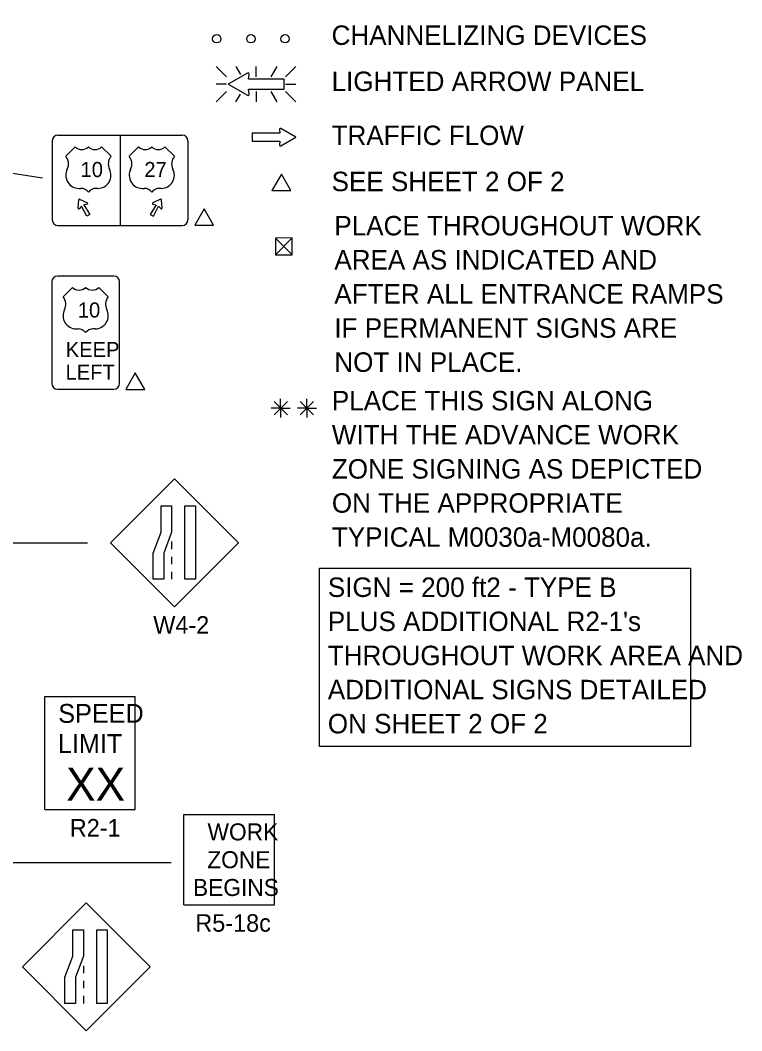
# Model space of a CAD drawing. Extents: x 16731 to 18475, y 7005 to 8303.
# Drawn here: x 17095.5 to 17440.1, y 7483 to 7965.9 of the extents above; entities that cross this region are included whole.
import ezdxf

# ---------------------------------------------------------------- set-up
doc = ezdxf.new("R2010")
doc.units = 0
for name, color, linetype in [('ALI_LEGAL_EX', 7, 'Continuous'), ('MT_SCRATCH_LEVEL_E', 7, 'Continuous'), ('PAVT_EDGE_EX', 7, 'Continuous'), ('TRAFFIC_SIGNS_PR', 7, 'Continuous'), ('TYPICAL_EX', 7, 'Continuous'), ('TYPICAL_TEXT_DIMEN_EX', 7, 'Continuous'), ('TYPICAL_TEXT_DIMEN_PR', 7, 'Continuous')]:
    doc.layers.add(name, color=color, linetype=linetype)

msp = doc.modelspace()

# ---------------------------------------------------------------- linework, layer by layer
at = {"layer": 'ALI_LEGAL_EX'}
msp.add_arc((17317.23, 7890.11), 340, 129.5666, 180, dxfattribs=at)
at = {"layer": 'MT_SCRATCH_LEVEL_E'}
for p, q in [((17219.57, 7911.9), (17206.32, 7911.9)), ((17206.32, 7911.9), (17206.32, 7908.16)), ((17219.57, 7911.9), (17206.32, 7911.9)), ((17206.32, 7911.9), (17206.32, 7908.16)), ((17219.26, 7913.68), (17219.57, 7911.9)), ((17219.26, 7913.68), (17219.57, 7911.9)), ((17227.18, 7910.05), (17219.94, 7914.16)), ((17227.18, 7910.05), (17219.94, 7914.16)), ((17219.94, 7905.9), (17227.18, 7910.05)), ((17219.94, 7905.9), (17227.18, 7910.05)), ((17206.32, 7908.16), (17219.57, 7908.16)), ((17206.32, 7908.16), (17219.57, 7908.16)), ((17219.57, 7908.16), (17219.26, 7906.38)), ((17219.57, 7908.16), (17219.26, 7906.38))]:
    msp.add_line(p, q, dxfattribs=at)
for centre, start, end in [((17219.72, 7913.75), 60.4248, 189.9638), ((17219.72, 7913.75), 60.4248, 189.9638), ((17219.72, 7906.31), 170.0362, 299.7731), ((17219.72, 7906.31), 170.0362, 299.7731)]:
    msp.add_arc(centre, 0.463, start, end, dxfattribs=at)
at = {"layer": 'PAVT_EDGE_EX'}
for radius in [316, 300]:
    msp.add_arc((17317.23, 7890.11), radius, 110.7433, 180, dxfattribs=at)
at = {"layer": 'TRAFFIC_SIGNS_PR'}
for p, q in [((17189.03, 7943.86), (17193.97, 7938.93)), ((17200.8, 7940.04), (17198.59, 7943.86)), ((17208.12, 7938.93), (17208.12, 7943.86)), ((17215.35, 7938.93), (17218.2, 7943.86)), ((17222.26, 7938.93), (17227.2, 7943.87)), ((17193.97, 7935.37), (17189.03, 7935.37)), ((17222.26, 7935.37), (17227.2, 7935.37)), ((17189.03, 7926.89), (17193.97, 7931.82)), ((17198.54, 7926.88), (17200.66, 7930.55)), ((17208.12, 7931.82), (17208.12, 7926.88)), ((17218.24, 7926.88), (17215.4, 7931.82)), ((17222.26, 7931.82), (17227.2, 7926.88)), ((17113.5, 7911), (17172.9, 7911)), ((17143.2, 7911), (17143.2, 7867.8)), ((17110.8, 7908.3), (17110.8, 7870.5)), ((17175.6, 7908.3), (17175.6, 7870.5)), ((17123.15, 7876.07), (17123.47, 7880.14)), ((17123.89, 7880.39), (17127.58, 7878.62)), ((17162.51, 7880.39), (17158.82, 7878.62)), ((17163.25, 7876.07), (17162.93, 7880.14)), ((17113.5, 7867.8), (17172.9, 7867.8)), ((17140.26, 7843.65), (17113.26, 7843.65)), ((17110.56, 7840.95), (17110.56, 7792.35)), ((17142.96, 7792.35), (17142.96, 7840.95)), ((17113.26, 7789.65), (17140.26, 7789.65)), ((17169.22, 7746.75), (17138.67, 7716.2)), ((17199.76, 7716.2), (17169.22, 7746.75)), ((17167.81, 7716.76), (17167.81, 7713.16)), ((17138.67, 7716.2), (17169.22, 7685.66)), ((17169.22, 7685.66), (17199.76, 7716.2)), ((17167.81, 7709.56), (17167.81, 7705.96)), ((17167.81, 7702.36), (17167.81, 7698.76)), ((17107.18, 7642.73), (17150.38, 7642.73)), ((17107.18, 7588.73), (17107.18, 7642.73)), ((17150.38, 7588.73), (17150.38, 7642.73)), ((17107.18, 7588.73), (17150.38, 7588.73)), ((17173.72, 7543.24), (17173.72, 7586.44)), ((17173.72, 7586.44), (17216.92, 7586.44)), ((17216.92, 7543.24), (17216.92, 7586.44)), ((17127.07, 7544.14), (17096.52, 7513.59)), ((17157.62, 7513.59), (17127.07, 7544.14)), ((17173.72, 7543.24), (17216.92, 7543.24)), ((17096.52, 7513.59), (17127.07, 7483.04)), ((17125.67, 7514.14), (17125.67, 7510.54)), ((17127.07, 7483.04), (17157.62, 7513.59)), ((17125.67, 7506.94), (17125.67, 7503.34)), ((17125.67, 7499.74), (17125.67, 7496.14))]:
    msp.add_line(p, q, dxfattribs=at)
for points in [[(17204.04, 7940.65), (17194.75, 7935.37), (17204.05, 7930.05)], [(17204.92, 7930.68), (17204.52, 7932.95), (17221.53, 7932.95), (17221.53, 7937.75), (17204.52, 7937.75), (17204.92, 7940.03)], [(17127.53, 7878.08), (17125.95, 7877.64), (17128.78, 7873.16), (17127.28, 7872.3), (17124.82, 7876.99), (17123.65, 7875.84)], [(17158.87, 7878.08), (17160.45, 7877.64), (17157.62, 7873.16), (17159.12, 7872.3), (17161.58, 7876.99), (17162.75, 7875.84)]]:
    msp.add_lwpolyline(points, dxfattribs=at)
for points in [[(17167.81, 7733.91), (17167.81, 7721.33), (17164.05, 7711.34), (17164.05, 7698.76), (17159, 7698.76), (17159, 7711.34), (17162.76, 7721.33), (17162.76, 7733.91)], [(17179.22, 7733.91), (17179.22, 7698.76), (17174.16, 7698.76), (17174.16, 7733.91)], [(17125.67, 7531.29), (17125.67, 7518.72), (17121.9, 7508.72), (17121.9, 7496.14), (17116.85, 7496.14), (17116.85, 7508.72), (17120.61, 7518.72), (17120.61, 7531.29)], [(17137.07, 7531.29), (17137.07, 7496.14), (17132.02, 7496.14), (17132.02, 7531.29)]]:
    msp.add_lwpolyline(points, close=True, dxfattribs=at)
for centre in [(17189.38, 7957.06), (17205.68, 7957.06), (17221.98, 7957.06)]:
    msp.add_circle(centre, 2, dxfattribs=at)
for centre, radius, start, end in [((17204.33, 7940.13), 0.598, 350.7308, 118.8916), ((17204.33, 7930.58), 0.597, 241.4833, 9.9593), ((17113.5, 7908.3), 2.7, 90, 180), ((17113.5, 7908.3), 2.7, 90, 180), ((17172.9, 7908.3), 2.7, 0, 90), ((17123.44, 7876.05), 0.293, 175.5177, 314.0115), ((17123.76, 7880.12), 0.293, 64.4823, 175.5177), ((17127.45, 7878.36), 0.293, 285.9885, 64.4823), ((17158.95, 7878.36), 0.293, 115.5177, 254.0115), ((17162.64, 7880.12), 0.293, 4.4823, 115.5177), ((17162.96, 7876.05), 0.293, 225.9885, 4.4823), ((17113.5, 7870.5), 2.7, 180, 270), ((17172.9, 7870.5), 2.7, 270, 0), ((17113.26, 7840.95), 2.7, 90, 180), ((17140.26, 7840.95), 2.7, 0, 90), ((17113.26, 7792.35), 2.7, 180, 270), ((17140.26, 7792.35), 2.7, 270, 0)]:
    msp.add_arc(centre, radius, start, end, dxfattribs=at)
at = {"layer": 'TYPICAL_EX'}
for p, q in [((17117.27, 7900.88), (17121.77, 7905.38)), ((17138.87, 7900.88), (17134.37, 7905.38)), ((17147.53, 7900.88), (17152.03, 7905.38)), ((17169.13, 7900.88), (17164.63, 7905.38)), ((17123.56, 7885.57), (17124.46, 7885.57)), ((17132.57, 7885.57), (17131.67, 7885.57)), ((17153.82, 7885.57), (17154.72, 7885.57)), ((17162.84, 7885.57), (17161.94, 7885.57)), ((17115.96, 7833.75), (17120.46, 7838.25)), ((17137.56, 7833.75), (17133.06, 7838.25)), ((17122.25, 7818.44), (17123.15, 7818.44)), ((17131.26, 7818.44), (17130.36, 7818.44))]:
    msp.add_line(p, q, dxfattribs=at)
for centre, radius, start, end in [((17124.92, 7908.65), 4.55, 226.1404, 313.8596), ((17131.22, 7908.65), 4.55, 226.1404, 313.8596), ((17155.18, 7908.65), 4.55, 226.1404, 313.8596), ((17161.48, 7908.65), 4.55, 226.1404, 313.8596), ((17113, 7897.27), 5.58, 333.0977, 40.1936), ((17143.13, 7897.27), 5.58, 139.8064, 206.9023), ((17143.27, 7897.27), 5.58, 333.0977, 40.1936), ((17173.4, 7897.27), 5.58, 139.8064, 206.9023), ((17123.57, 7891.86), 6.29, 152.6698, 269.9013), ((17132.56, 7891.86), 6.29, 270.0987, 27.3302), ((17153.84, 7891.86), 6.29, 152.6698, 269.9013), ((17162.83, 7891.86), 6.29, 270.0987, 27.3302), ((17124.47, 7881.06), 4.51, 37.1038, 90.1385), ((17131.66, 7881.06), 4.51, 89.8615, 142.8962), ((17154.74, 7881.06), 4.51, 37.1038, 90.1385), ((17161.93, 7881.06), 4.51, 89.8615, 142.8962), ((17123.61, 7841.53), 4.55, 226.1404, 313.8596), ((17129.91, 7841.53), 4.55, 226.1404, 313.8596), ((17111.69, 7830.15), 5.58, 333.0977, 40.1936), ((17141.82, 7830.15), 5.58, 139.8064, 206.9023), ((17122.26, 7824.73), 6.29, 152.6698, 269.9013), ((17131.25, 7824.73), 6.29, 270.0987, 27.3302), ((17123.16, 7813.93), 4.51, 37.1038, 90.1385), ((17130.35, 7813.93), 4.51, 89.8615, 142.8962)]:
    msp.add_arc(centre, radius, start, end, dxfattribs=at)
at = {"layer": 'TYPICAL_TEXT_DIMEN_EX'}
msp.add_lwpolyline([(17238.37, 7704.17), (17415.64, 7704.17), (17415.64, 7618.85), (17238.37, 7618.85)], close=True, dxfattribs=at)
at = {"layer": 'TYPICAL_TEXT_DIMEN_PR'}
for p, q in [((16958.58, 7913.46), (17106.19, 7890.54)), ((17217.35, 7853.86), (17225.35, 7861.86)), ((17217.36, 7861.85), (17225.35, 7853.86)), ((17219.89, 7780.57), (17219.89, 7785.02)), ((17232.45, 7780.57), (17232.45, 7785.02)), ((17219.89, 7780.57), (17215.36, 7780.57)), ((17216.71, 7783.76), (17223.08, 7777.38)), ((17223.08, 7783.76), (17216.71, 7777.38)), ((17219.89, 7780.57), (17223.08, 7780.57)), ((17219.89, 7780.57), (17224.37, 7780.57)), ((17219.89, 7780.57), (17219.89, 7776.07)), ((17232.45, 7780.57), (17227.92, 7780.57)), ((17229.26, 7783.76), (17235.64, 7777.38)), ((17235.64, 7783.76), (17229.26, 7777.38)), ((17232.45, 7780.57), (17235.64, 7780.57)), ((17232.45, 7780.57), (17236.93, 7780.57)), ((17232.45, 7780.57), (17232.45, 7776.07)), ((17127.56, 7716), (17091.79, 7716)), ((17040.33, 7563.44), (17167.53, 7563.44))]:
    msp.add_line(p, q, dxfattribs=at)
for points in [[(17220.25, 7892.34), (17215.72, 7884.51), (17224.77, 7884.51)], [(17183.34, 7875.75), (17178.82, 7867.92), (17187.87, 7867.92)], [(17217.36, 7861.85), (17217.35, 7853.86), (17225.35, 7853.86), (17225.35, 7861.86)], [(17150.45, 7797.35), (17145.92, 7789.51), (17154.97, 7789.51)]]:
    msp.add_lwpolyline(points, close=True, dxfattribs=at)
msp.add_arc((17317.23, 7890.11), 256, 135.9481, 167.0592, dxfattribs=at)

# ---------------------------------------------------------------- texts
at = {"layer": 'TRAFFIC_SIGNS_PR'}
for s, height, p in [('10', 7.2, (17124.31, 7890.98)), ('27', 7.2, (17154.77, 7890.98)), ('10', 7.2, (17123, 7823.85)), ('KEEP', 7.2, (17117.24, 7804.95)), ('LEFT', 7.2, (17117.14, 7794.15)), ('W4-2', 8.37, (17159.04, 7672.79)), ('SPEED', 9, (17113.67, 7630.2)), ('LIMIT', 9, (17113.49, 7615.8)), ('XX', 15.785, (17117.43, 7592.96)), ('R2-1', 8.37, (17119.19, 7575.86)), ('WORK', 8.119, (17184.97, 7574.03)), ('ZONE', 8.119, (17184.84, 7560.74)), ('BEGINS', 8.119, (17178.01, 7547.46)), ('R5-18c', 8.37, (17179.13, 7530.37))]:
    msp.add_text(s, height=height, dxfattribs=at).set_placement(p)
at = {"layer": 'TYPICAL_TEXT_DIMEN_EX'}
for s, p in [('CHANNELIZING DEVICES', (17244.22, 7954.12)), ('LIGHTED ARROW PANEL', (17244.22, 7932.07)), ('TRAFFIC FLOW', (17244.22, 7906.27)), ('SEE SHEET 2 OF 2', (17244.22, 7884.22)), ('PLACE THROUGHOUT WORK', (17245.53, 7863.1)), ('AREA AS INDICATED AND', (17245.53, 7846.8)), ('AFTER ALL ENTRANCE RAMPS', (17245.53, 7830.5)), ('IF PERMANENT SIGNS ARE', (17245.53, 7814.2)), ('NOT IN PLACE.', (17245.53, 7797.9)), ('PLACE THIS SIGN ALONG', (17244.35, 7779.49)), ('WITH THE ADVANCE WORK', (17244.35, 7763.19)), ('ZONE SIGNING AS DEPICTED', (17244.35, 7746.89)), ('ON THE APPROPRIATE', (17244.35, 7730.59)), ('TYPICAL M0030a-M0080a.', (17244.35, 7714.29)), ('SIGN = 200 ft2 - TYPE B', (17242.42, 7690.34)), ("PLUS ADDITIONAL R2-1's", (17242.42, 7674.04)), ('THROUGHOUT WORK AREA AND', (17242.42, 7657.74)), ('ADDITIONAL SIGNS DETAILED', (17242.42, 7641.44)), ('ON SHEET 2 OF 2', (17242.42, 7625.14))]:
    msp.add_text(s, height=9.3, dxfattribs=at).set_placement(p)

doc.saveas('drawing.dxf')
